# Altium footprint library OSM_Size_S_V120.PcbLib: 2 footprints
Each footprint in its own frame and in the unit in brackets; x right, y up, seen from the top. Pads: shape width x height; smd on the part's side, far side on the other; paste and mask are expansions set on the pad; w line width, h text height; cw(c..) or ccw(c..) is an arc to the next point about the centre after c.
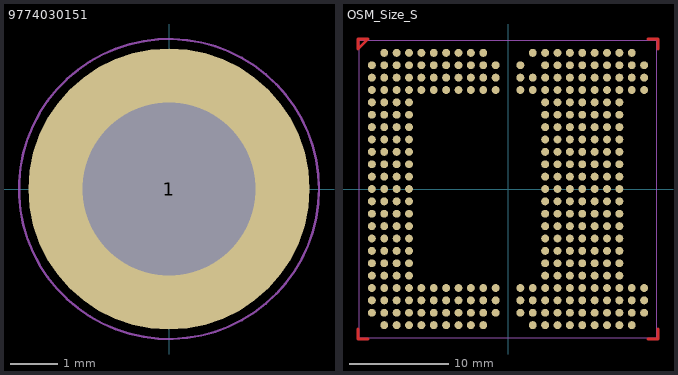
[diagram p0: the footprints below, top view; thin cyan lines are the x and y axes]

## 9774030151 [mm] "SMT Steel Spacer with internal Thread M2.5, height 3mm"
height 3
pads (1):
  round 6 / inner round 0 / far side round 3.9 hole 3.7 unplated: 1(0,0)
Top Paste:
  region: 0.325,2.902 0.57,2.874 1.044,2.738 1.488,2.524 1.89,2.239 2.239,1.89 2.524,1.488 2.738,1.044 2.874,0.57 2.902,0.325 1.872,0.325 1.842,0.467 1.749,0.743 1.615,1.002 1.443,1.237 1.237,1.442 1.002,1.614 0.744,1.748 0.468,1.842 0.325,1.872
  region: 2.902,-0.325 2.874,-0.57 2.738,-1.044 2.524,-1.488 2.239,-1.89 1.89,-2.239 1.488,-2.524 1.044,-2.738 0.57,-2.874 0.325,-2.902 0.325,-1.872 0.467,-1.842 0.743,-1.749 1.002,-1.615 1.237,-1.443 1.442,-1.237 1.614,-1.002 1.748,-0.744 1.842,-0.468 1.872,-0.325
  region: -0.325,-2.902 -0.57,-2.874 -1.044,-2.738 -1.488,-2.524 -1.89,-2.239 -2.239,-1.89 -2.524,-1.488 -2.738,-1.044 -2.874,-0.57 -2.902,-0.325 -1.872,-0.325 -1.842,-0.467 -1.749,-0.743 -1.615,-1.002 -1.443,-1.237 -1.237,-1.442 -1.002,-1.614 -0.744,-1.748 -0.468,-1.842 -0.325,-1.872
  region: -2.902,0.325 -2.874,0.57 -2.738,1.044 -2.524,1.488 -2.239,1.89 -1.89,2.239 -1.488,2.524 -1.044,2.738 -0.57,2.874 -0.325,2.902 -0.325,1.872 -0.467,1.842 -0.743,1.749 -1.002,1.615 -1.237,1.443 -1.442,1.237 -1.614,1.002 -1.748,0.744 -1.842,0.468 -1.872,0.325
Top Assembly:
  circle w0.1: c0,0 r2.55
Top Component Outline:
  circle w0.1: c0,0 r2.55
Top Courtyard:
  circle w0.05: c0,0 r3.2
  lines w0.05: -0.5,0 0.5,0 ; 0,-0.5 0,0.5
3D body "9774030151.stp": height 3, standoff -1.4, extent -2.55,-2.547 2.55,2.547

## OSM_Size_S [mm]
pads (332):
  round 0.8 smd mask+0: A2(-12.5,13.75) A3(-11.25,13.75) A4(-10,13.75) A5(-8.75,13.75) A6(-7.5,13.75) A7(-6.25,13.75) A8(-5,13.75) A9(-3.75,13.75) A10(-2.5,13.75) A14(2.5,13.75) A15(3.75,13.75) A16(5,13.75) A17(6.25,13.75) A18(7.5,13.75) A19(8.75,13.75) A20(10,13.75) A21(11.25,13.75) A22(12.5,13.75) AA1(-13.75,-11.25) AA2(-12.5,-11.25) AA3(-11.25,-11.25) AA4(-10,-11.25) AA5(-8.75,-11.25) AA6(-7.5,-11.25) AA7(-6.25,-11.25) AA8(-5,-11.25) AA9(-3.75,-11.25) AA10(-2.5,-11.25) AA11(-1.25,-11.25) AA13(1.25,-11.25) AA14(2.5,-11.25) AA15(3.75,-11.25) AA16(5,-11.25) AA17(6.25,-11.25) AA18(7.5,-11.25) AA19(8.75,-11.25) AA20(10,-11.25) AA21(11.25,-11.25) AA22(12.5,-11.25) AA23(13.75,-11.25) AB1(-13.75,-12.5) AB2(-12.5,-12.5) AB3(-11.25,-12.5) AB4(-10,-12.5) AB5(-8.75,-12.5) AB6(-7.5,-12.5) AB7(-6.25,-12.5) AB8(-5,-12.5) AB9(-3.75,-12.5) AB10(-2.5,-12.5) AB11(-1.25,-12.5) AB13(1.25,-12.5) AB14(2.5,-12.5) AB15(3.75,-12.5) AB16(5,-12.5) AB17(6.25,-12.5) AB18(7.5,-12.5) AB19(8.75,-12.5) AB20(10,-12.5) AB21(11.25,-12.5) AB22(12.5,-12.5) AB23(13.75,-12.5) AC2(-12.5,-13.75) AC3(-11.25,-13.75) AC4(-10,-13.75) AC5(-8.75,-13.75) AC6(-7.5,-13.75) AC7(-6.25,-13.75) AC8(-5,-13.75) AC9(-3.75,-13.75) AC10(-2.5,-13.75) AC14(2.5,-13.75) AC15(3.75,-13.75) AC16(5,-13.75) AC17(6.25,-13.75) AC18(7.5,-13.75) AC19(8.75,-13.75) AC20(10,-13.75) AC21(11.25,-13.75) AC22(12.5,-13.75) B1(-13.75,12.5) B2(-12.5,12.5) B3(-11.25,12.5) B4(-10,12.5) B5(-8.75,12.5) B6(-7.5,12.5) B7(-6.25,12.5) B8(-5,12.5) B9(-3.75,12.5) B10(-2.5,12.5) B11(-1.25,12.5) B13(1.25,12.5) B15(3.75,12.5) B16(5,12.5) B17(6.25,12.5) B18(7.5,12.5) B19(8.75,12.5) B20(10,12.5) B21(11.25,12.5) B22(12.5,12.5) B23(13.75,12.5) C1(-13.75,11.25) C2(-12.5,11.25) C3(-11.25,11.25) C4(-10,11.25) C5(-8.75,11.25) C6(-7.5,11.25) C7(-6.25,11.25) C8(-5,11.25) C9(-3.75,11.25) C10(-2.5,11.25) C11(-1.25,11.25) C13(1.25,11.25) C14(2.5,11.25) C15(3.75,11.25) C16(5,11.25) C17(6.25,11.25) C18(7.5,11.25) C19(8.75,11.25) C20(10,11.25) C21(11.25,11.25) C22(12.5,11.25) C23(13.75,11.25) D1(-13.75,10) D2(-12.5,10) D3(-11.25,10) D4(-10,10) D5(-8.75,10) D6(-7.5,10) D7(-6.25,10) D8(-5,10) D9(-3.75,10) D10(-2.5,10) D11(-1.25,10) D13(1.25,10) D14(2.5,10) D15(3.75,10) D16(5,10) D17(6.25,10) D18(7.5,10) D19(8.75,10) D20(10,10) D21(11.25,10) D22(12.5,10) D23(13.75,10) E1(-13.75,8.75) E2(-12.5,8.75) E3(-11.25,8.75) E4(-10,8.75) E15(3.75,8.75) E16(5,8.75) E17(6.25,8.75) E18(7.5,8.75) E19(8.75,8.75) E20(10,8.75) E21(11.25,8.75) F1(-13.75,7.5) F2(-12.5,7.5) F3(-11.25,7.5) F4(-10,7.5) F15(3.75,7.5) F16(5,7.5) F17(6.25,7.5) F18(7.5,7.5) F19(8.75,7.5) F20(10,7.5) F21(11.25,7.5) G1(-13.75,6.25) G2(-12.5,6.25) G3(-11.25,6.25) G4(-10,6.25) G15(3.75,6.25) G16(5,6.25) G17(6.25,6.25) G18(7.5,6.25) G19(8.75,6.25) G20(10,6.25) G21(11.25,6.25) H1(-13.75,5) H2(-12.5,5) H3(-11.25,5) H4(-10,5) H15(3.75,5) H16(5,5) H17(6.25,5) H18(7.5,5) H19(8.75,5) H20(10,5) H21(11.25,5) J1(-13.75,3.75) J2(-12.5,3.75) J3(-11.25,3.75) J4(-10,3.75) J15(3.75,3.75) J16(5,3.75) J17(6.25,3.75) J18(7.5,3.75) J19(8.75,3.75) J20(10,3.75) J21(11.25,3.75) K1(-13.75,2.5) K2(-12.5,2.5) K3(-11.25,2.5) K4(-10,2.5) K15(3.75,2.5) K16(5,2.5) K17(6.25,2.5) K18(7.5,2.5) K19(8.75,2.5) K20(10,2.5) K21(11.25,2.5) L1(-13.75,1.25) L2(-12.5,1.25) L3(-11.25,1.25) L4(-10,1.25) L15(3.75,1.25) L16(5,1.25) L17(6.25,1.25) L18(7.5,1.25) L19(8.75,1.25) L20(10,1.25) L21(11.25,1.25) M1(-13.75,0) M2(-12.5,0) M3(-11.25,0) M4(-10,0) M15(3.75,0) M16(5,0) M17(6.25,0) M18(7.5,0) M19(8.75,0) M20(10,0) M21(11.25,0) N1(-13.75,-1.25) N2(-12.5,-1.25) N3(-11.25,-1.25) N4(-10,-1.25) N15(3.75,-1.25) N16(5,-1.25) N17(6.25,-1.25) N18(7.5,-1.25) N19(8.75,-1.25) N20(10,-1.25) N21(11.25,-1.25) P1(-13.75,-2.5) P2(-12.5,-2.5) P3(-11.25,-2.5) P4(-10,-2.5) P15(3.75,-2.5) P16(5,-2.5) P17(6.25,-2.5) P18(7.5,-2.5) P19(8.75,-2.5) P20(10,-2.5) P21(11.25,-2.5) R1(-13.75,-3.75) R2(-12.5,-3.75) R3(-11.25,-3.75) R4(-10,-3.75) R15(3.75,-3.75) R16(5,-3.75) R17(6.25,-3.75) R18(7.5,-3.75) R19(8.75,-3.75) R20(10,-3.75) R21(11.25,-3.75) T1(-13.75,-5) T2(-12.5,-5) T3(-11.25,-5) T4(-10,-5) T15(3.75,-5) T16(5,-5) T17(6.25,-5) T18(7.5,-5) T19(8.75,-5) T20(10,-5) T21(11.25,-5) U1(-13.75,-6.25) U2(-12.5,-6.25) U3(-11.25,-6.25) U4(-10,-6.25) U15(3.75,-6.25) U16(5,-6.25) U17(6.25,-6.25) U18(7.5,-6.25) U19(8.75,-6.25) U20(10,-6.25) U21(11.25,-6.25) V1(-13.75,-7.5) V2(-12.5,-7.5) V3(-11.25,-7.5) V4(-10,-7.5) V15(3.75,-7.5) V16(5,-7.5) V17(6.25,-7.5) V18(7.5,-7.5) V19(8.75,-7.5) V20(10,-7.5) V21(11.25,-7.5) W1(-13.75,-8.75) W2(-12.5,-8.75) W3(-11.25,-8.75) W4(-10,-8.75) W15(3.75,-8.75) W16(5,-8.75) W17(6.25,-8.75) W18(7.5,-8.75) W19(8.75,-8.75) W20(10,-8.75) W21(11.25,-8.75) Y1(-13.75,-10) Y2(-12.5,-10) Y3(-11.25,-10) Y4(-10,-10) Y5(-8.75,-10) Y6(-7.5,-10) Y7(-6.25,-10) Y8(-5,-10) Y9(-3.75,-10) Y10(-2.5,-10) Y11(-1.25,-10) Y13(1.25,-10) Y14(2.5,-10) Y15(3.75,-10) Y16(5,-10) Y17(6.25,-10) Y18(7.5,-10) Y19(8.75,-10) Y20(10,-10) Y21(11.25,-10) Y22(12.5,-10) Y23(13.75,-10)
Top Layer:
  lines w0.3: -15.15,-14.15 -15.15,-15.15 -14.15,-15.15 ; 14.15,-15.15 15.15,-15.15 15.15,-14.15 ; 14.15,15.15 15.15,15.15 15.15,14.15 ; -15.15,14.15 -15.15,15.15 -14.15,15.15 -15.15,14.15
Top Assembly:
  lines w0.1: -15,-15 -15,15 15,15 15,-15 -15,-15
